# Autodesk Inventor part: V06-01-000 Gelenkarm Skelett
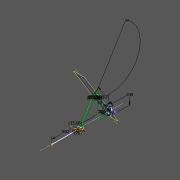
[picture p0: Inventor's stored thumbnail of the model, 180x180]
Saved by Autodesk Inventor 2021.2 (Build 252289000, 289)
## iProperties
RuleStatus: InUse
Company: R-Kon - Rodermund Konstruktion und Entwicklung GmbH
Created: 2020-09
Part Number: V06-01-000 Gelenkarm Skelett
Material: Stahl
Document SubType Name: Modeling
Designer: Felix Rodermund
Engineer: Felix Rodermund
Density: 7.85 g/cm^3
Appearance: Stahl
StatusCheck: 1
Title: Teil
Author: Felix Rodermund
Revision Number: 0
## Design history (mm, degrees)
sketch "yz Befestigung und Weg" dims "d6" = 2.73648 (derived), "d30" = 70 (derived)
  geometry: L1 (-100, 0.229)-(100, 0.229); L2 (0, 1200.229)-(0, 700.229); L3 (0, -240.046)-(0, 1440.275) reference; 2 further points
  constraints: 4 end point, 2 point on line, 1 horizontal, 1 midpoint, 1 vertical
  dimensions: "d1" = 200 distance of L1.start L1.end; "d2" = 700 distance from line of L1 L2.end; "Hub" = 500 distance of L2.start L2.end
sketch "yz Armgeometrie"
  geometry: L1 (0, 70.229)-(455.878, 350.229); L2 (455.878, 350.229)-(0, 630.229); L3 (0, -240.046)-(0, 1440.275) reference; L4 (0, 1200.229)-(0, 700.229) reference; L5 (-100, 0.229)-(100, 0.229) reference; L6 (0, 70.229)-(72.973, 600.229); L7 (72.973, 600.229)-(0, 1130.229); L8 (434.944, 384.314)-(-20.935, 104.314); L9 (476.813, 316.145)-(20.935, 36.145); L10 (40, 700.229)-(-40, 700.229); L11 (0, 630.229)-(0, 700.229); L12 (40, 680.229)-(-40, 680.229); L13 (0, 1130.229)-(0, 1200.229); L14 (40, 1200.229)-(-40, 1200.229); A1 r 40 centre (455.878, 350.229) between (476.813, 316.145) and (434.944, 384.314); A2 r 40 centre (0, 70.229) between (20.935, 36.145) and (-20.935, 104.314); 3 further points
  constraints: 22 end point, 6 equal length, 4 point on circle, 4 tangent, 3 coincident, 3 midpoint, 3 point on line, 2 centre point, 2 horizontal, 2 parallel, 2 perpendicular, 1 collinear, 1 vertical, 1 vertical alignment, 3 other
  dimensions: "d4" = 70 distance from line of L5 L1.start; "d5" = 535 distance of L1.start L1.end; "d6" = 15.6789 deg angle of L7 L6 (derived); "d7" = 80 distance between parallel lines of L9 L8; "d26" = 80 distance of L10.start L10.end; "d28" = 20 distance between parallel lines of L10 L12; "d29" = 10 distance from line of point (0, 670.229) L12; "d30" = 70 distance of L11.start L4.end (derived)
sketch "xz Befestigungslager"
  geometry: L1 (-100, 0)-(100, 0); L2 (100, 0)-(100, 20); L3 (100, 20)-(-100, 20); L4 (-100, 20)-(-100, 0); L5 (140, 0)-(-140, 0) reference; L6 (-15, 20)-(-15, 110.229); L7 (-15, 110.229)-(15, 110.229); L8 (15, 110.229)-(15, 20); L9 (0, 110.229)-(0, 30.229) reference; L10 (-37, 310.229)-(-37, 30.229); L11 (-37, 30.229)-(-17, 30.229); L12 (-17, 30.229)-(-17, 113.229); L13 (-17, 113.229)-(17, 113.229); L14 (17, 113.229)-(17, 30.229); L15 (17, 30.229)-(37, 30.229); L16 (37, 30.229)-(37, 310.229); L17 (0, 390.229)-(0, 310.229) reference; 6 further points
  constraints: 28 end point, 8 perpendicular, 5 point on line, 4 midpoint, 2 collinear, 2 horizontal alignment, 2 parallel, 2 vertical, 1 horizontal, 4 other
  dimensions: "d8" = 20 distance of L1.end L2.end; "d9" = 200 distance of L2.end L3.end; "d10" = 30 distance of L6.end L7.end; "d11" = 2 distance between parallel lines of L14 L8; "d12" = 3 distance between parallel lines of L13 L7; "d13" = 20 distance of L14.end L15.end
node "ewx Mitte Armsegment"
sketch "wx Armgelenk"
  geometry: L1 (20.935, 15)-(20.935, -15) reference; L2 (20.935, -15)-(-26.288, -15) reference; L3 (-26.288, 15)-(20.935, 15) reference; L4 (-20.935, -17)-(-20.935, -37) reference; L5 (22.505, -17)-(-20.935, -17) reference; L6 (-20.935, -37)-(125.607, -37) reference; L7 (485, 37)-(485, 15); L8 (485, 15)-(575, 15); L9 (575, 15)-(575, -15); L10 (575, -15)-(485, -15); L11 (485, -15)-(485, -37); L12 (-353.223, 0)-(1265.573, 0) reference; L13 (575, 0)-(495, 0) reference; 2 further points
  constraints: 10 end point, 5 point on line, 3 perpendicular, 2 midpoint, 1 collinear, 1 vertical
  dimensions: "d15" = 10 distance from line of L11 L13.end
sketch "yz Befestigungslager"
  geometry: L1 (40, 20)-(40, 70.229); L2 (-40, 20)-(-40, 70.229); L3 (0, 20)-(0, 0) reference; L4 (0, 20)-(0, 110.229) reference; L5 (100, 20)-(-100, 20); L6 (-100, 20)-(-100, 0); L7 (-100, 0)-(100, 0); L8 (100, 0)-(100, 20); L9 (-100, 0.229)-(100, 0.229) reference; A1 r 40 centre (0, 70.229) between (40, 70.229) and (-40, 70.229); 2 further points
  constraints: 12 end point, 4 point on line, 3 point on circle, 2 midpoint, 2 parallel, 2 tangent, 2 vertical, 1 centre point, 1 coincident, 1 horizontal, 1 perpendicular, 1 vertical alignment
node "x Hubanfang"
node "exy Hub Ende"
node "exy Hub Anfang"
sketch "xz Gelenkdetails" dims "d6" = 2.73648 (derived), "d30" = 70 (derived)
  geometry: L1 (-37, 310.229)-(-37, 30.229) reference; L2 (-37, 30.229)-(-17, 30.229) reference; L3 (-17, 30.229)-(-17, 113.229) reference; L4 (-15, 20)-(-15, 110.229) reference; L5 (-15, 110.229)-(15, 110.229) reference; L6 (15, 110.229)-(15, 20) reference; L7 (37, 30.229)-(37, 310.229) reference; L8 (47, 82.729)-(-47, 82.729); L9 (-47, 82.729)-(-47, 57.729); L10 (-47, 57.729)-(47, 57.729); L11 (47, 57.729)-(47, 82.729); L12 (-15, 57.229)-(15, 57.229); L13 (47, 70.229)-(-47, 70.229); 2 further points
  constraints: 12 end point, 3 midpoint, 2 parallel, 2 perpendicular, 2 point on line, 1 horizontal
  dimensions: "d16" = 10 distance between parallel lines of L7 L11; "d17" = 10 distance between parallel lines of L1 L9; "d18" = 0.5 distance between parallel lines of L10 L12; "d19" = 25 distance of L8.end L9.end
sketch "yz Kollision" dims "d6" = 2.73648 (derived), "d30" = 70 (derived)
  geometry: L1 (434.944, 384.314)-(-20.935, 104.314) reference; L2 (476.813, 316.145)-(20.935, 36.145) reference; L3 (20.935, 664.314)-(476.813, 384.314); L4 (-20.935, 596.145)-(434.944, 316.145); L5 (434.944, 316.145)-(476.813, 384.314); L6 (392.338, 358.145)-(434.207, 289.977); L7 (378.42, 349.597)-(416.709, 326.171); L8 (-300.984, -114.635)-(1078.406, 732.585) reference; A1 r 40 centre (455.878, 350.229) between (434.944, 384.314) and (476.813, 316.145) reference; 6 further points; 1 other entity
  constraints: 10 end point, 4 point on line, 2 equal length, 2 midpoint, 2 perpendicular, 1 coincident, 1 parallel, 2 other
  dimensions: "d20" = 80 distance between parallel lines of L4 L3 (= d21); "d21" = 80 distance between parallel lines of L1 L2 (derived); "d22" = 116.884 deg angle of L1 L4 (derived); "d23" = 1 distance from line of L4 L7.end; "d24" = 0.1 deg angle of L7 L4; "d25" = 116.984 deg angle of L1 L7 (derived)
sketch "xz Konsole" dims "d6" = 2.73648 (derived), "d30" = 70 (derived)
  geometry: L1 (-15, 371.164)-(15, 371.164) reference; L2 (-37, 30.229)-(-17, 30.229) reference; L3 (-47, 57.729)-(47, 57.729) reference; L4 (-47, 82.729)-(-47, 57.729) reference; L5 (47, 82.729)-(-47, 82.729) reference; L6 (47, 70.229)-(-47, 70.229) reference; L7 (47, 700.229)-(-47, 700.229); L8 (-47, 700.229)-(-47, 680.229); L9 (-47, 680.229)-(47, 680.229); L10 (47, 680.229)-(47, 700.229); L11 (-37, 680.229)-(-37, 590.229); L12 (-37, 590.229)-(-17, 590.229); L13 (-17, 590.229)-(-17, 680.229); L14 (15, 670.229)-(-15, 670.229); L15 (-15, 670.229)-(-15, 590.229); L16 (-15, 590.229)-(15, 590.229); L17 (15, 590.229)-(15, 670.229); L18 (0, 670.229)-(0, 590.229) reference; L19 (47, 642.729)-(-47, 642.729); L20 (-47, 642.729)-(-47, 617.729); L21 (-47, 617.729)-(47, 617.729); L22 (47, 617.729)-(47, 642.729); L23 (47, 630.229)-(-47, 630.229); 5 further points
  constraints: 32 end point, 7 midpoint, 6 parallel, 5 perpendicular, 4 point on line, 3 equal length, 3 horizontal, 2 collinear, 1 coincident, 1 vertical
  dimensions: "d31" = 10 distance between parallel lines of L11 L8
sketch "yz Armsegment Details"
  geometry: C1 r 40 at (455.878, 350.229) reference; C2 r 13 at (455.878, 350.229); 4 further points
  constraints: 2 coincident, 1 centre point, 1 vertical alignment, 3 other
node "Volumenkörper1"
other parameters: "d14" = 90 deg
